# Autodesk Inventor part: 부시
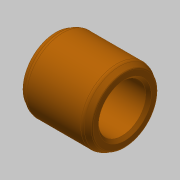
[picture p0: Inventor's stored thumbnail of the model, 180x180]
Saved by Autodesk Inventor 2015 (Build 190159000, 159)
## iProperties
Created: 2018-11
Part Number: 부시
Material: 강철, 연강
Document SubType Name: Modeling
Designer: mduedu
Density: 1 g/cm^3
Appearance: 주황색
Author: mduedu
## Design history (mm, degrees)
sketch "스케치1"
  geometry: C1 r 8.5 at (0, 0); C2 r 13 at (0, 0); 1 further point
  constraints: 2 centre point, 2 coincident
  dimensions: "d0" = 17 diameter of C1; "d1" = 26 diameter of C2
extrude "돌출1" new body sketch "스케치1" distance "d2" = 25; taper "d3" = 0 deg
chamfer "모따기4" distance "d14" = 1; stored, may be unused: second distance "d15" = 2, angle "d16" = 15 deg
chamfer "모따기5" distance "d17" = 2.3; stored, may be unused: second distance "d18" = 2, angle "d19" = 30 deg
chamfer "모따기6" distance "d20" = 2.3; stored, may be unused: second distance "d21" = 2, angle "d22" = 30 deg
fillet "모깎기2" dims "d23" = 2, "d24" = 0.5
fillet "모깎기3" dims "d25" = 2, "d26" = 0.5
node "솔리드1"
